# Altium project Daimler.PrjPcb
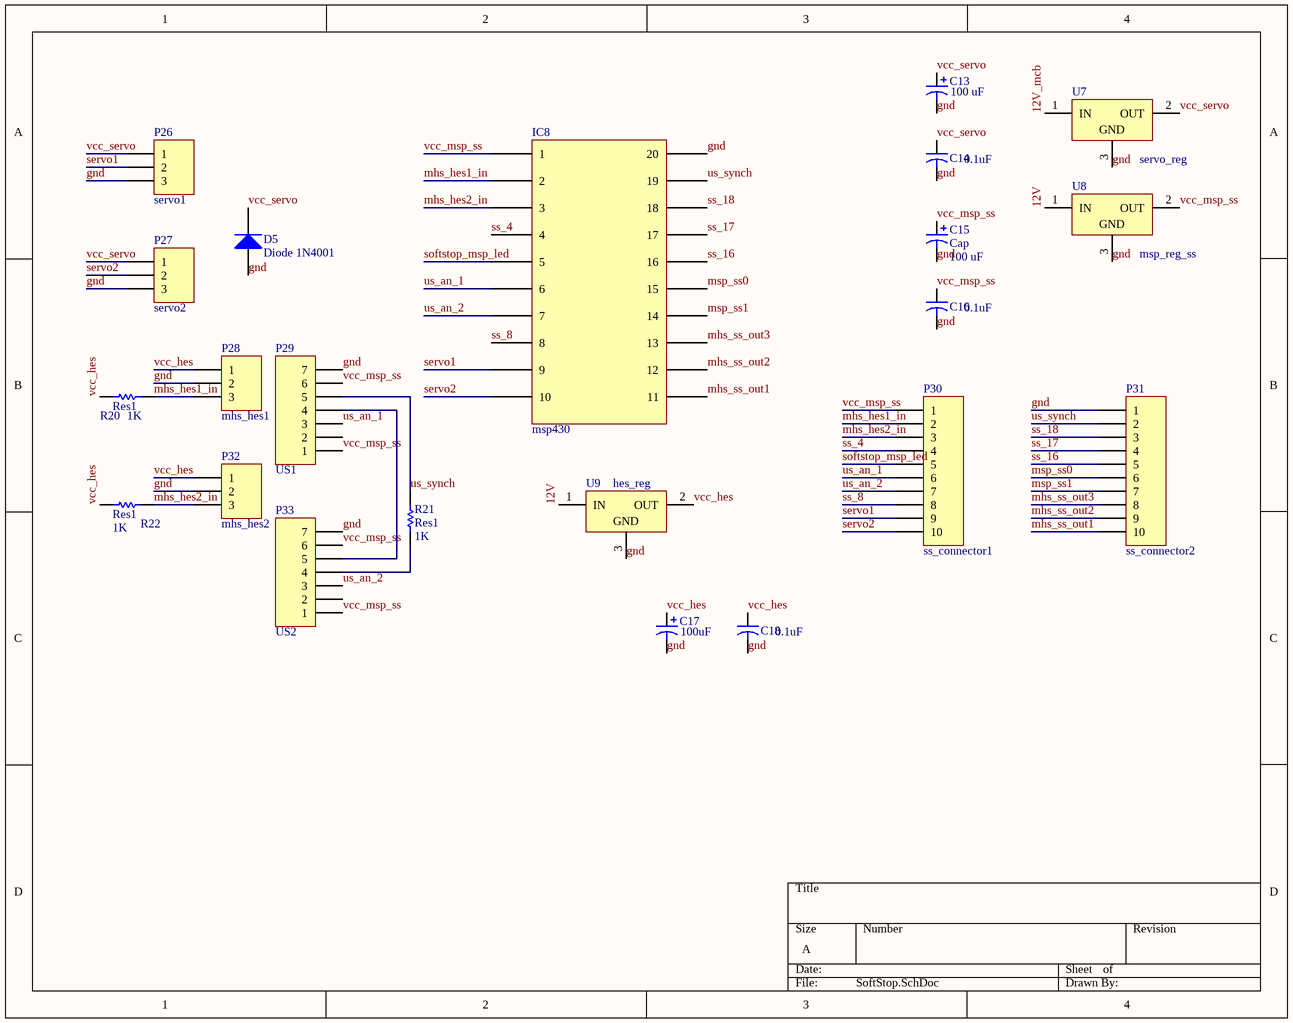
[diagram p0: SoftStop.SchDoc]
5 sheets, 112 parts. Net scope: global (net labels, ports and power ports of the same name join across sheets).
Board file: Daimler.PcbDoc
Sheets:
  SoftStop.SchDoc
  RPi.SchDoc
  HardStop.SchDoc
  Safety.SchDoc
  Navigation.SchDoc

## Sheet SoftStop.SchDoc
size A

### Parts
C13  value 100 uF  [RB7.6-15]  (hidden comment: Cap)
C14  value 0.1uF  [CAPR5-4X5]  (hidden comment: Cap2)
C15  Cap  value 100 uF  [RB7.6-15]
C16  value 0.1uF  [CAPR5-4X5]  (hidden comment: Cap2)
C17  value 100uF  [RB7.6-15]  (hidden comment: Cap Pol1)
C18  value 0.1uF  [CAPR5-4X5]  (hidden comment: Cap2)
D5  Diode 1N4001  [DO-41]
IC8  msp430  [msp430]
P26  servo1  [HDR1X3H]
P27  servo2  [HDR1X3H]
P28  mhs_hes1  [HDR1X3H]
P29  US1  [HDR1X7H]
P30  ss_connector1  [HDR1X10]
P31  ss_connector2  [HDR1X10]
P32  mhs_hes2  [HDR1X3H]
P33  US2  [HDR1X7H]
R20  Res1  value 1K  [AXIAL-0.3]
R21  Res1  value 1K  [AXIAL-0.3]
R22  Res1  value 1K  [AXIAL-0.3]
U7  servo_reg  [TO220ABN]
U8  msp_reg_ss  [TO220ABN]
U9  hes_reg  [TO220ABN]

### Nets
12V: U8.1(IN) U9.1(IN)
12V_mcb: U7.1(IN)
gnd: C13.2 C14.2 C15.2 C16.2 C17.2 C18.2 D5.1(A) IC8.20 P26.3 P27.3 P28.2 P29.7 P31.1 P32.2 P33.7 U7.3(GND) U8.3(GND) U9.3(GND)
mhs_hes1_in: IC8.2 P28.3 P30.2 R20.2
mhs_hes2_in: IC8.3 P30.3 P32.3 R22.2
mhs_ss_out1: IC8.11 P31.10
mhs_ss_out2: IC8.12 P31.9
mhs_ss_out3: IC8.13 P31.8
msp_ss0: IC8.15 P31.6
msp_ss1: IC8.14 P31.7
servo1: IC8.9 P26.2 P30.9
servo2: IC8.10 P27.2 P30.10
softstop_msp_led: IC8.5 P30.5
ss_4: IC8.4 P30.4
ss_8: IC8.8 P30.8
ss_16: IC8.16 P31.5
ss_17: IC8.17 P31.4
ss_18: IC8.18 P31.3
us_an_1: IC8.6 P29.3 P30.6
us_an_2: IC8.7 P30.7 P33.3
us_synch: IC8.19 P29.5 P31.2 R21.2
vcc_hes: C17.1 C18.1 P28.1 P32.1 R20.1 R22.1 U9.2(OUT)
vcc_msp_ss: C15.1 C16.1 IC8.1 P29.1 P29.6 P30.1 P33.1 P33.6 U8.2(OUT)
vcc_servo: C13.1 C14.1 D5.2(K) P26.1 P27.1 U7.2(OUT)
NetP29_4: P29.4 P33.5
NetP33_4: P33.4 R21.1

Not connected (* = marked no-connect by the designer): P29 2; P33 2

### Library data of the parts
C13 C15 C17 = Cap Pol1: Polarized Capacitor (Radial)
C14 C16 C18 = Cap2: Capacitor
D5 = Diode 1N4001: 1 Amp General Purpose Rectifier
P26-P28 P32 = Header 3H: Header, 3-Pin, Right Angle
P29 P33 = Header 7H: Header, 7-Pin, Right Angle
P30 P31 = Header 10: Header, 10-Pin
R20-R22 = Res1: Resistor
U7-U9 = L7805CV: Positive Voltage Regulator; Note: Tab is connected to pin 3 (GND).

## Sheet RPi.SchDoc
size A
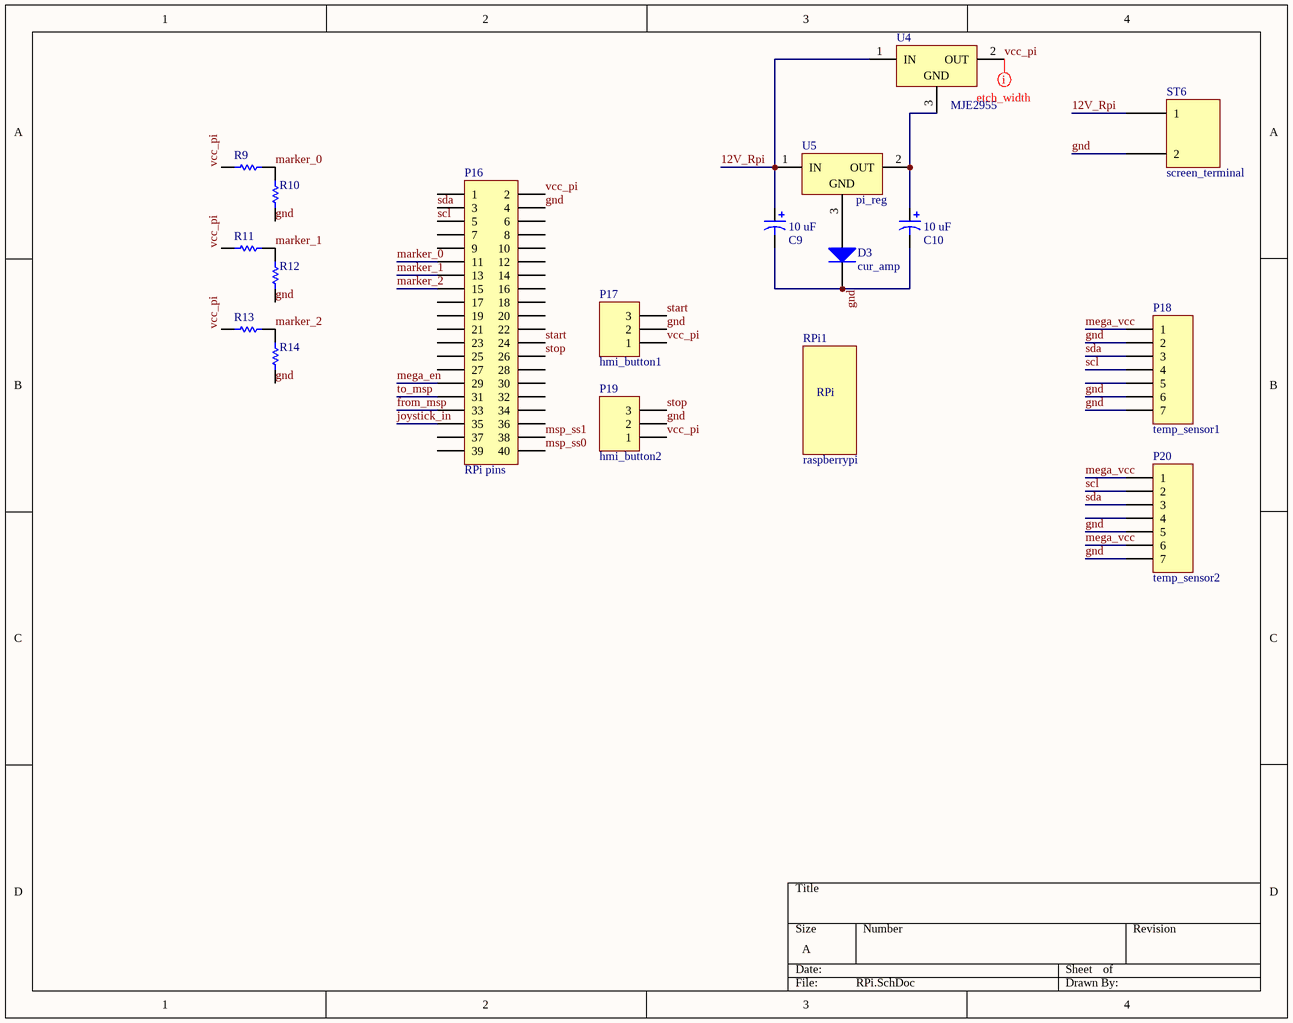
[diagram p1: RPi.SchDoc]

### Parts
C9  value 10 uF  [RB7.6-15]  (hidden comment: Cap)
C10  value 10 uF  [RB7.6-15]  (hidden comment: Cap)
D3  cur_amp  [DO-41]
P16  RPi pins  [HDR2X20]
P17  hmi_button1  [HDR1X3H]
P18  temp_sensor1  [HDR1X7H]
P19  hmi_button2  [HDR1X3H]
P20  temp_sensor2  [HDR1X7H]
R9  Res1  [AXIAL-0.3]  (value not drawn)
R10  Res1  [AXIAL-0.3]  (value not drawn)
R11  Res1  [AXIAL-0.3]  (value not drawn)
R12  Res1  [AXIAL-0.3]  (value not drawn)
R13  Res1  [AXIAL-0.3]  (value not drawn)
R14  Res1  [AXIAL-0.3]  (value not drawn)
RPi1  raspberrypi  [raspberrypi]
ST6  screen_terminal  [screw_terminal_5]
U4  MJE2955  [TO220ABN]
U5  pi_reg  [TO220ABN]

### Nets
12V_Rpi: C9.1 ST6.1 U4.1(IN) U5.1(IN)
from_msp: P16.33
gnd: C9.2 C10.2 D3.2(K) P16.4 P17.2 P18.2 P18.6 P18.7 P19.2 P20.5 P20.7 R10.2 R12.1 R14.1 ST6.2
joystick_in: P16.35
marker_0: P16.11 R9.2 R10.1
marker_1: P16.13 R11.2 R12.2
marker_2: P16.15 R13.2 R14.2
mega_en: P16.29
mega_vcc: P18.1 P20.1 P20.6
msp_ss0: P16.40
msp_ss1: P16.38
scl: P16.5 P18.4 P20.2
sda: P16.3 P18.3 P20.3
start: P16.24 P17.3
stop: P16.26 P19.3
to_msp: P16.31
vcc_pi: P16.2 P17.1 P19.1 R9.1 R11.1 R13.1 U4.2(OUT)
NetC10_1: C10.1 U4.3(GND) U5.2(OUT)
NetD3_1: D3.1(A) U5.3(GND)

Not connected (* = marked no-connect by the designer): P16 1 6 7 8 9 10 12 14 16 17 18 19 20 21 22 23 25 27 28 30 32 34 36 37 39; P18 5; P20 4

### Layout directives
rule Undefined; rule Width Constraint [Pref Width = 25mil    Min Width = 20mil    Max Width = 30mil]: vcc_pi

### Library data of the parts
C9 C10 = Cap Pol1: Polarized Capacitor (Radial)
D3 = Diode 1N4001: 1 Amp General Purpose Rectifier
P16 = Header 20X2: Header, 20-Pin, Dual row
P17 P19 = Header 3H: Header, 3-Pin, Right Angle
P18 P20 = Header 7H: Header, 7-Pin, Right Angle
R9-R14 = Res1: Resistor; Value: 1K
ST6 = screw_terminal
U4 U5 = L7805CV: as U7 on sheet SoftStop

## Sheet HardStop.SchDoc
size A
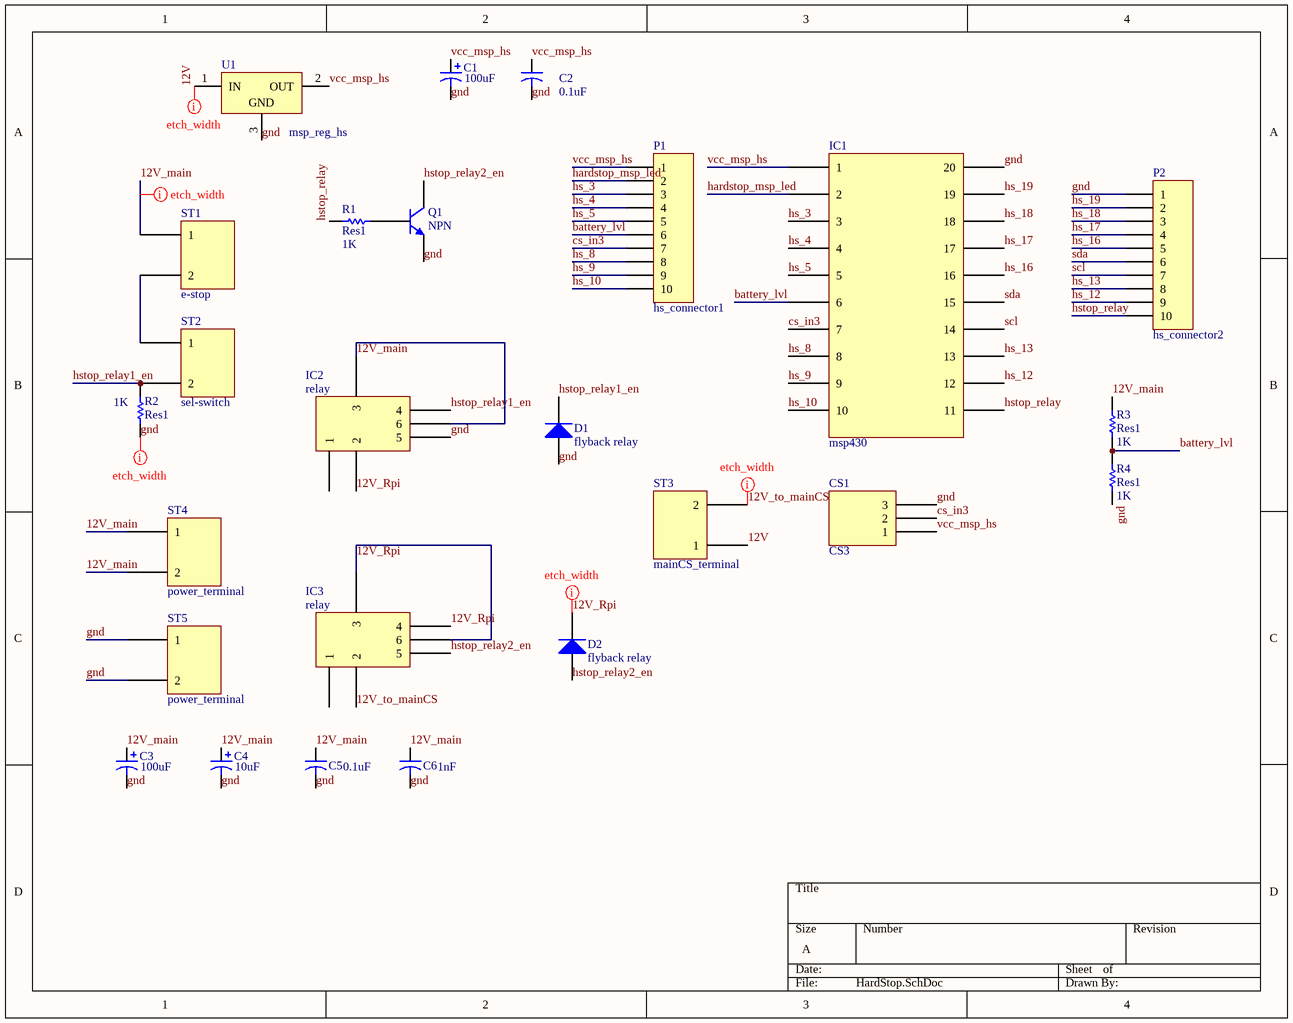
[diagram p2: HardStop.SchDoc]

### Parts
C1  value 100uF  [RB7.6-15]  (hidden comment: Cap Pol1)
C2  value 0.1uF  [CAPR5-4X5]  (hidden comment: Cap2)
C3  value 100uF  [RB7.6-15]  (hidden comment: Cap Pol1)
C4  value 10uF  [RB7.6-15]  (hidden comment: Cap Pol1)
C5  value 0.1uF  [CAPR5-4X5]  (hidden comment: Cap2)
C6  value 1nF  [CAPR5-4X5]  (hidden comment: Cap2)
CS1  CS3  [ACS712]
D1  flyback relay  [DO-41]
D2  flyback relay  [DO-41]
IC1  msp430  [msp430]
IC2  relay  [relay JQX 15F]
IC3  relay  [relay JQX 15F]
P1  hs_connector1  [HDR1X10]
P2  hs_connector2  [HDR1X10]
Q1  NPN  [TO-226-AA]
R1  Res1  value 1K  [AXIAL-0.3]
R2  Res1  value 1K  [AXIAL-0.3]
R3  Res1  value 1K  [AXIAL-0.3]
R4  Res1  value 1K  [AXIAL-0.3]
ST1  e-stop  [screw_terminal_5]
ST2  sel-switch  [screw_terminal_5]
ST3  mainCS_terminal  [screw_terminal_5]
ST4  power_terminal  [screw_terminal_5]
ST5  power_terminal  [screw_terminal_5]
U1  msp_reg_hs  [TO220ABN]

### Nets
12V: ST3.1 U1.1(IN)
12V_main: C3.1 C4.1 C5.1 C6.1 IC2.3 IC2.6 R3.1 ST1.1 ST4.1 ST4.2
12V_Rpi: D2.2(K) IC2.2 IC3.3 IC3.4 IC3.6
12V_to_mainCS: IC3.2 ST3.2
battery_lvl: IC1.6 P1.6 R3.2 R4.1
cs_in3: CS1.2 IC1.7 P1.7
gnd: C1.2 C2.2 C3.2 C4.2 C5.2 C6.2 CS1.3 D1.1(A) IC1.20 IC2.5 P2.1 Q1.3(E) R2.1 R4.2 ST5.1 ST5.2 U1.3(GND)
hardstop_msp_led: IC1.2 P1.2
hs_3: IC1.3 P1.3
hs_4: IC1.4 P1.4
hs_5: IC1.5 P1.5
hs_8: IC1.8 P1.8
hs_9: IC1.9 P1.9
hs_10: IC1.10 P1.10
hs_12: IC1.12 P2.9
hs_13: IC1.13 P2.8
hs_16: IC1.16 P2.5
hs_17: IC1.17 P2.4
hs_18: IC1.18 P2.3
hs_19: IC1.19 P2.2
hstop_relay: IC1.11 P2.10 R1.2
hstop_relay1_en: D1.2(K) IC2.4 R2.2 ST2.2
hstop_relay2_en: D2.1(A) IC3.5 Q1.1(C)
scl: IC1.14 P2.7
sda: IC1.15 P2.6
vcc_msp_hs: C1.1 C2.1 CS1.1 IC1.1 P1.1 U1.2(OUT)
NetQ1_2: Q1.2(B) R1.1
NetST1_2: ST1.2 ST2.1

Not connected (* = marked no-connect by the designer): IC2 1; IC3 1

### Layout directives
rule Undefined; rule Width Constraint [Pref Width = 75mil    Min Width = 70mil    Max Width = 80mil]: 12V, 12V_main, 12V_Rpi, 12V_to_mainCS, gnd

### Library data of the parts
C1 C3 C4 = Cap Pol1: Polarized Capacitor (Radial)
C2 C5 C6 = Cap2: Capacitor
CS1 = ACS712
D1 D2 = Diode 1N4001: 1 Amp General Purpose Rectifier
IC2 IC3 = relay JQX-15F
P1 P2 = Header 10: Header, 10-Pin
Q1 = NPN: NPN Bipolar Transistor
R1-R4 = Res1: Resistor
ST1-ST5 = screw_terminal
U1 = L7805CV: as U7 on sheet SoftStop

## Sheet Safety.SchDoc
size A
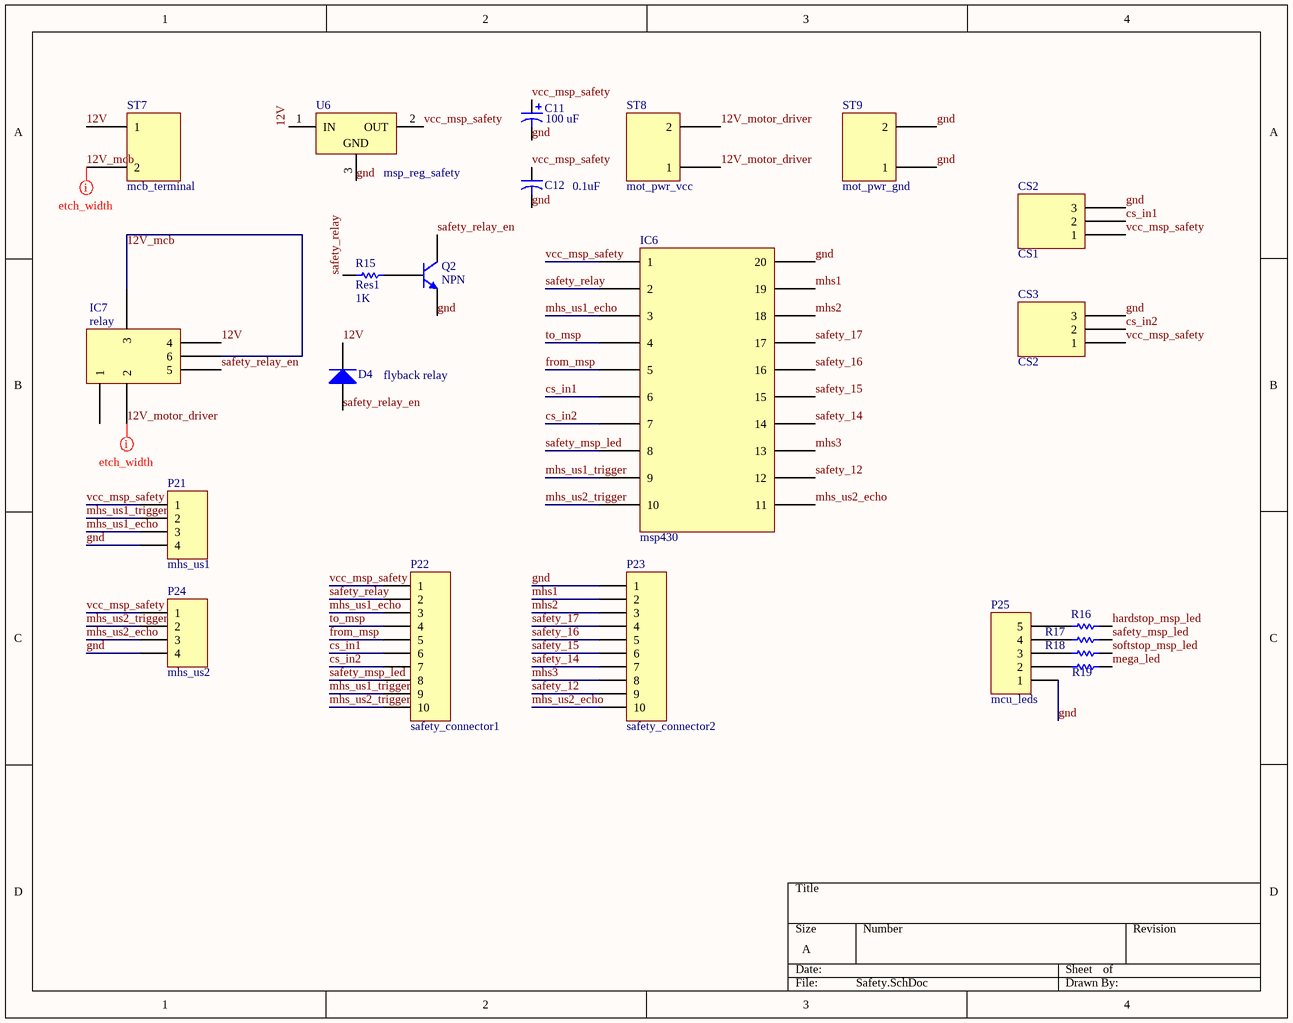
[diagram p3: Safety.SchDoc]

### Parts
C11  value 100 uF  [RB7.6-15]  (hidden comment: Cap)
C12  value 0.1uF  [CAPR5-4X5]  (hidden comment: Cap2)
CS2  CS1  [ACS712]
CS3  CS2  [ACS712]
D4  flyback relay  [DO-41]
IC6  msp430  [msp430]
IC7  relay  [relay JQX 15F]
P21  mhs_us1  [HDR1X4H]
P22  safety_connector1  [HDR1X10]
P23  safety_connector2  [HDR1X10]
P24  mhs_us2  [HDR1X4H]
P25  mcu_leds  [HDR1X5H]
Q2  NPN  [TO-226-AA]
R15  Res1  value 1K  [AXIAL-0.3]
R16  Res1  [AXIAL-0.3]  (value not drawn)
R17  Res1  [AXIAL-0.3]  (value not drawn)
R18  Res1  [AXIAL-0.3]  (value not drawn)
R19  Res1  [AXIAL-0.3]  (value not drawn)
ST7  mcb_terminal  [screw_terminal_5]
ST8  mot_pwr_vcc  [screw_terminal_5]
ST9  mot_pwr_gnd  [screw_terminal_5]
U6  msp_reg_safety  [TO220ABN]

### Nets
12V: D4.2(K) IC7.4 ST7.1 U6.1(IN)
12V_mcb: IC7.3 IC7.6 ST7.2
12V_motor_driver: IC7.2 ST8.1 ST8.2
cs_in1: CS2.2 IC6.6 P22.6
cs_in2: CS3.2 IC6.7 P22.7
from_msp: IC6.5 P22.5
gnd: C11.2 C12.2 CS2.3 CS3.3 IC6.20 P21.4 P23.1 P24.4 P25.1 Q2.3(E) ST9.1 ST9.2 U6.3(GND)
hardstop_msp_led: R16.1
mega_led: R19.1
mhs1: IC6.19 P23.2
mhs2: IC6.18 P23.3
mhs3: IC6.13 P23.8
mhs_us1_echo: IC6.3 P21.3 P22.3
mhs_us1_trigger: IC6.9 P21.2 P22.9
mhs_us2_echo: IC6.11 P23.10 P24.3
mhs_us2_trigger: IC6.10 P22.10 P24.2
safety_12: IC6.12 P23.9
safety_14: IC6.14 P23.7
safety_15: IC6.15 P23.6
safety_16: IC6.16 P23.5
safety_17: IC6.17 P23.4
safety_msp_led: IC6.8 P22.8 R17.1
safety_relay: IC6.2 P22.2 R15.2
safety_relay_en: D4.1(A) IC7.5 Q2.1(C)
softstop_msp_led: R18.1
to_msp: IC6.4 P22.4
vcc_msp_safety: C11.1 C12.1 CS2.1 CS3.1 IC6.1 P21.1 P22.1 P24.1 U6.2(OUT)
NetP25_2: P25.2 R19.2
NetP25_3: P25.3 R18.2
NetP25_4: P25.4 R17.2
NetP25_5: P25.5 R16.2
NetQ2_2: Q2.2(B) R15.1

Not connected (* = marked no-connect by the designer): IC7 1

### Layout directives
rule Undefined; rule Width Constraint [Pref Width = 75mil    Min Width = 70mil    Max Width = 80mil]: 12V_mcb, 12V_motor_driver

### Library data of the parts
C11 = Cap Pol1: Polarized Capacitor (Radial)
C12 = Cap2: Capacitor
CS2 CS3 = ACS712
D4 = Diode 1N4001: 1 Amp General Purpose Rectifier
IC7 = relay JQX-15F
P21 P24 = Header 4H: Header, 4-Pin, Right Angle
P22 P23 = Header 10: Header, 10-Pin
P25 = Header 5H: Header, 5-Pin, Right Angle
Q2 = NPN: NPN Bipolar Transistor
R15 = Res1: Resistor
R16-R19 = Res1: Resistor; Value: 1K
ST7-ST9 = screw_terminal
U6 = L7805CV: as U7 on sheet SoftStop

## Sheet Navigation.SchDoc
size A
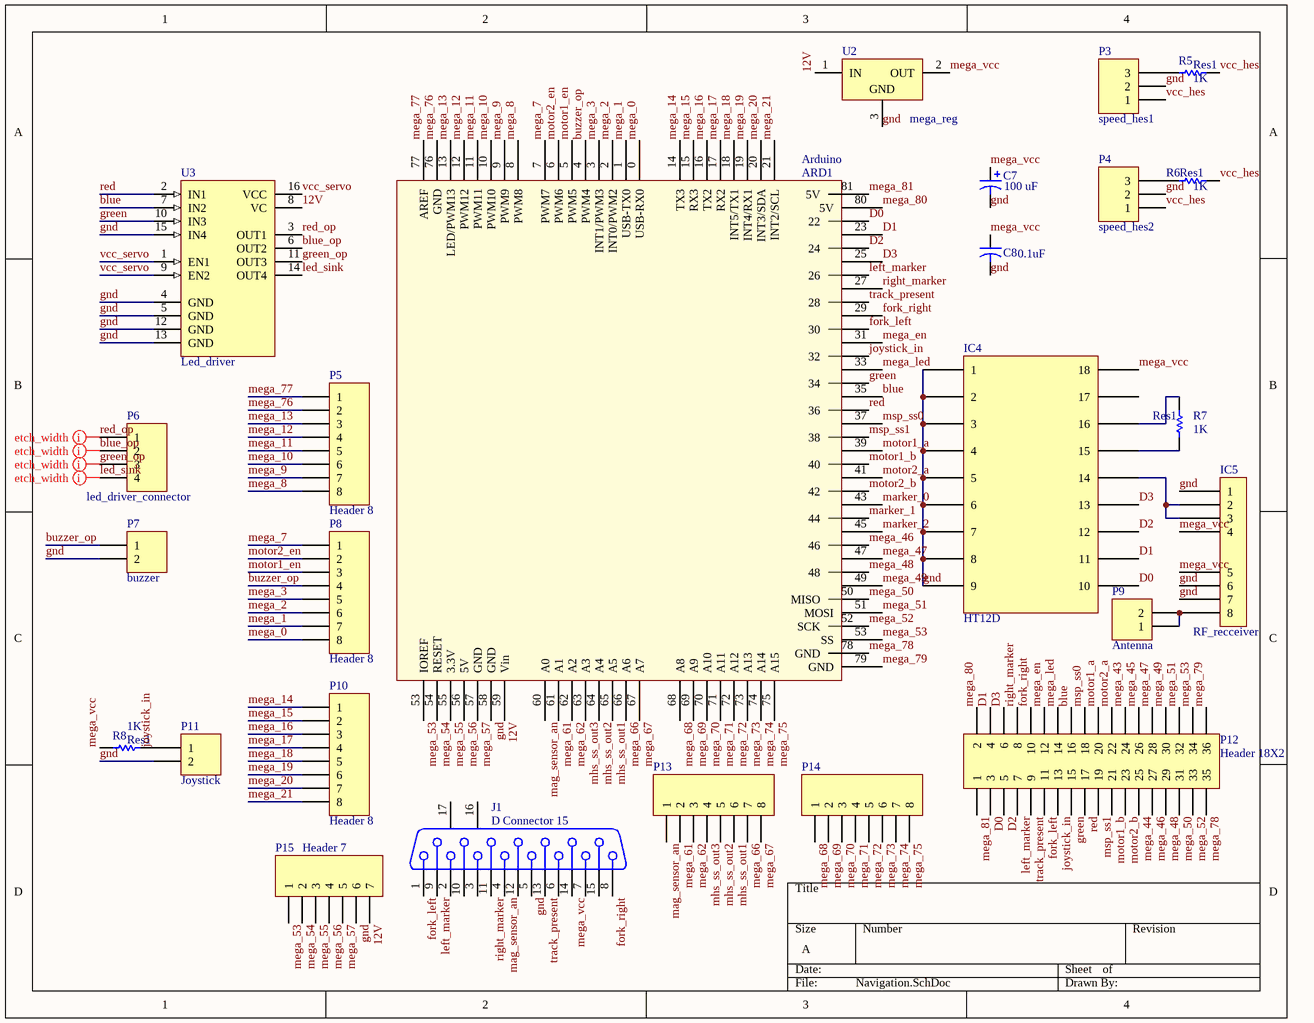
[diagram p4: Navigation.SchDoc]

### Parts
ARD1  Arduino  [Arduino]
C7  value 100 uF  [RB7.6-15]  (hidden comment: Cap)
C8  value 0.1uF  [CAPR5-4X5]  (hidden comment: Cap2)
IC4  HT12D  [HT12D]
IC5  RF_recceiver  [RF_434_receiver]
J1  D Connector 15  [DSUB1.385-2H15]
P3  speed_hes1  [HDR1X3H]
P4  speed_hes2  [HDR1X3H]
P5  Header 8  [HDR1X8]
P6  led_driver_connector  [HDR1X4H]
P7  buzzer  [HDR1X2H]
P8  Header 8  [HDR1X8]
P9  Antenna  [HDR1X2H]
P10  Header 8  [HDR1X8]
P11  Joystick  [HDR1X2H]
P12  Header 18X2  [HDR2X18]
P13  Header 8  [HDR1X8]  (value not drawn)
P14  Header 8  [HDR1X8]  (value not drawn)
P15  Header 7  [HDR1X7]
R5  Res1  value 1K  [AXIAL-0.3]
R6  Res1  value 1K  [AXIAL-0.3]
R7  Res1  value 1K  [AXIAL-0.3]
R8  Res1  value 1K  [AXIAL-0.3]
U2  mega_reg  [TO220ABN]
U3  Led_driver  [DIP16]

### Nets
12V: ARD1.59(Vin) P15.7 U2.1(IN) U3.8(VC)
blue: ARD1.35 P12.16 U3.7(IN2)
blue_op: P6.2 U3.6(OUT2)
buzzer_op: ARD1.4(PWM4) P7.1 P8.4
D0: ARD1.22 IC4.10 P12.3
D1: ARD1.23 IC4.11 P12.4
D2: ARD1.24 IC4.12 P12.5
D3: ARD1.25 IC4.13 P12.6
fork_left: ARD1.30 J1.1 P12.11
fork_right: ARD1.29 J1.8 P12.10
gnd: ARD1.58(GND) C7.2 C8.2 IC4.1 IC4.2 IC4.3 IC4.4 IC4.5 IC4.6 IC4.7 IC4.8 IC4.9 IC5.1 IC5.6 IC5.7 J1.5 P3.2 P4.2 P7.2 P11.2 P15.6 U2.3(GND) U3.4(GND) U3.5(GND) U3.12(GND) U3.13(GND) U3.15(IN4)
green: ARD1.34 P12.15 U3.10(IN3)
green_op: P6.3 U3.11(OUT3)
joystick_in: ARD1.32 P11.1 P12.13 R8.2
led_sink: P6.4 U3.14(OUT4)
left_marker: ARD1.26 J1.9 P12.7
mag_sensor_an: ARD1.60(A0) J1.4 P13.1
marker_0: ARD1.43
marker_1: ARD1.44
marker_2: ARD1.45
mega_0: ARD1.0(USB-RX0) P8.8
mega_1: ARD1.1(USB-TX0) P8.7
mega_2: ARD1.2(INT0/PWM2) P8.6
mega_3: ARD1.3(INT1/PWM3) P8.5
mega_7: ARD1.7(PWM7) P8.1
mega_8: ARD1.8(PWM8) P5.8
mega_9: ARD1.9(PWM9) P5.7
mega_10: ARD1.10(PWM10) P5.6
mega_11: ARD1.11(PWM11) P5.5
mega_12: ARD1.12(PWM12) P5.4
mega_13: ARD1.13(LED/PWM13) P5.3
mega_14: ARD1.14(TX3) P10.1
mega_15: ARD1.15(RX3) P10.2
mega_16: ARD1.16(TX2) P10.3
mega_17: ARD1.17(RX2) P10.4
mega_18: ARD1.18(INT5/TX1) P10.5
mega_19: ARD1.19(INT4/RX1) P10.6
mega_20: ARD1.20(INT3/SDA) P10.7
mega_21: ARD1.21(INT2/SCL) P10.8
mega_43: P12.24
mega_44: P12.25
mega_45: P12.26
mega_46: ARD1.46 P12.27
mega_47: ARD1.47 P12.28
mega_48: ARD1.48 P12.29
mega_49: ARD1.49 P12.30
mega_50: ARD1.50(MISO) P12.31
mega_51: ARD1.51(MOSI) P12.32
mega_52: ARD1.52(SCK) P12.33
mega_53: ARD1.53(SS) P12.34 P15.1
mega_54: ARD1.54(RESET) P15.2
mega_55: ARD1.55(3.3V) P15.3
mega_56: ARD1.56(5V) P15.4
mega_57: ARD1.57(GND) P15.5
mega_61: ARD1.61(A1) P13.2
mega_62: ARD1.62(A2) P13.3
mega_66: ARD1.66(A6) P13.7
mega_67: ARD1.67(A7) P13.8
mega_68: ARD1.68(A8) P14.1
mega_69: ARD1.69(A9) P14.2
mega_70: ARD1.70(A10) P14.3
mega_71: ARD1.71(A11) P14.4
mega_72: ARD1.72(A12) P14.5
mega_73: ARD1.73(A13) P14.6
mega_74: ARD1.74(A14) P14.7
mega_75: ARD1.75(A15) P14.8
mega_76: ARD1.76(GND) P5.2
mega_77: ARD1.77(AREF) P5.1
mega_78: ARD1.78(GND) P12.35
mega_79: ARD1.79(GND) P12.36
mega_80: ARD1.80(5V) P12.2
mega_81: ARD1.81(5V) P12.1
mega_en: ARD1.31 P12.12
mega_led: ARD1.33 P12.14
mega_vcc: C7.1 C8.1 IC4.18 IC5.4 IC5.5 J1.14 R8.1 U2.2(OUT)
mhs_ss_out1: ARD1.65(A5) P13.6
mhs_ss_out2: ARD1.64(A4) P13.5
mhs_ss_out3: ARD1.63(A3) P13.4
motor1_a: ARD1.39 P12.20
motor1_b: ARD1.40 P12.21
motor1_en: ARD1.5(PWM5) P8.3
motor2_a: ARD1.41 P12.22
motor2_b: ARD1.42 P12.23
motor2_en: ARD1.6(PWM6) P8.2
msp_ss0: ARD1.37 P12.18
msp_ss1: ARD1.38 P12.19
red: ARD1.36 P12.17 U3.2(IN1)
red_op: P6.1 U3.3(OUT1)
right_marker: ARD1.27 J1.11 P12.8
track_present: ARD1.28 J1.13 P12.9
vcc_hes: P3.1 P4.1 R5.2 R6.2
vcc_servo: U3.1(EN1) U3.9(EN2) U3.16(VCC)
NetIC4_14: IC4.14 IC5.2 IC5.3
NetIC4_15: IC4.15 R7.2
NetIC4_16: IC4.16 R7.1
NetIC5_8: IC5.8 P9.1 P9.2
NetP3_3: P3.3 R5.1
NetP4_3: P4.3 R6.1

Not connected (* = marked no-connect by the designer): IC4 17; J1 2 3 6 7 10 12 15 16(MH1) 17(MH2)

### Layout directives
rule Undefined; rule Width Constraint [Pref Width = 25mil    Min Width = 20mil    Max Width = 30mil]: blue_op, green_op, led_sink, red_op

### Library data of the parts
C7 = Cap Pol1: Polarized Capacitor (Radial)
C8 = Cap2: Capacitor
IC5 = RF434_receiver
J1 = D Connector 15: Receptacle Assembly, 15 Position, Right Angle; PackageDocument: O; Positions: 15
P3 P4 = Header 3H: Header, 3-Pin, Right Angle
P5 P8 P10 P13 P14 = Header 8: Header, 8-Pin
P6 = Header 4H: Header, 4-Pin, Right Angle
P7 P9 P11 = Header 2H: Header, 2-Pin, Right Angle
P12 = Header 18X2: Header, 18-Pin, Dual row
P15 = Header 7: Header, 7-Pin
R5-R8 = Res1: Resistor
U2 = L7805CV: as U7 on sheet SoftStop
U3 = L293D: Push-Pull Four Channel Driver With Diode

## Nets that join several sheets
12V: SoftStop (U8.1 U9.1), HardStop (ST3.1 U1.1), Safety (D4.2 IC7.4 ST7.1 U6.1), Navigation (ARD1.59 P15.7 U2.1 U3.8)
12V_mcb: SoftStop (U7.1), Safety (IC7.3 IC7.6 ST7.2)
12V_Rpi: RPi (C9.1 ST6.1 U4.1 U5.1), HardStop (5 pins)
from_msp: RPi (P16.33), Safety (IC6.5 P22.5)
gnd: SoftStop (18 pins), RPi (15 pins), HardStop (17 pins), Safety (13 pins), Navigation (27 pins)
hardstop_msp_led: HardStop (IC1.2 P1.2), Safety (R16.1)
joystick_in: RPi (P16.35), Navigation (ARD1.32 P11.1 P12.13 R8.2)
marker_0: RPi (P16.11 R9.2 R10.1), Navigation (ARD1.43)
marker_1: RPi (P16.13 R11.2 R12.2), Navigation (ARD1.44)
marker_2: RPi (P16.15 R13.2 R14.2), Navigation (ARD1.45)
mega_en: RPi (P16.29), Navigation (ARD1.31 P12.12)
mega_led: Safety (R19.1), Navigation (ARD1.33 P12.14)
mega_vcc: RPi (P18.1 P20.1 P20.6), Navigation (8 pins)
mhs_ss_out1: SoftStop (IC8.11 P31.10), Navigation (ARD1.65 P13.6)
mhs_ss_out2: SoftStop (IC8.12 P31.9), Navigation (ARD1.64 P13.5)
mhs_ss_out3: SoftStop (IC8.13 P31.8), Navigation (ARD1.63 P13.4)
msp_ss0: SoftStop (IC8.15 P31.6), RPi (P16.40), Navigation (ARD1.37 P12.18)
msp_ss1: SoftStop (IC8.14 P31.7), RPi (P16.38), Navigation (ARD1.38 P12.19)
scl: RPi (P16.5 P18.4 P20.2), HardStop (IC1.14 P2.7)
sda: RPi (P16.3 P18.3 P20.3), HardStop (IC1.15 P2.6)
softstop_msp_led: SoftStop (IC8.5 P30.5), Safety (R18.1)
to_msp: RPi (P16.31), Safety (IC6.4 P22.4)
vcc_hes: SoftStop (7 pins), Navigation (P3.1 P4.1 R5.2 R6.2)
vcc_servo: SoftStop (6 pins), Navigation (U3.1 U3.9 U3.16)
